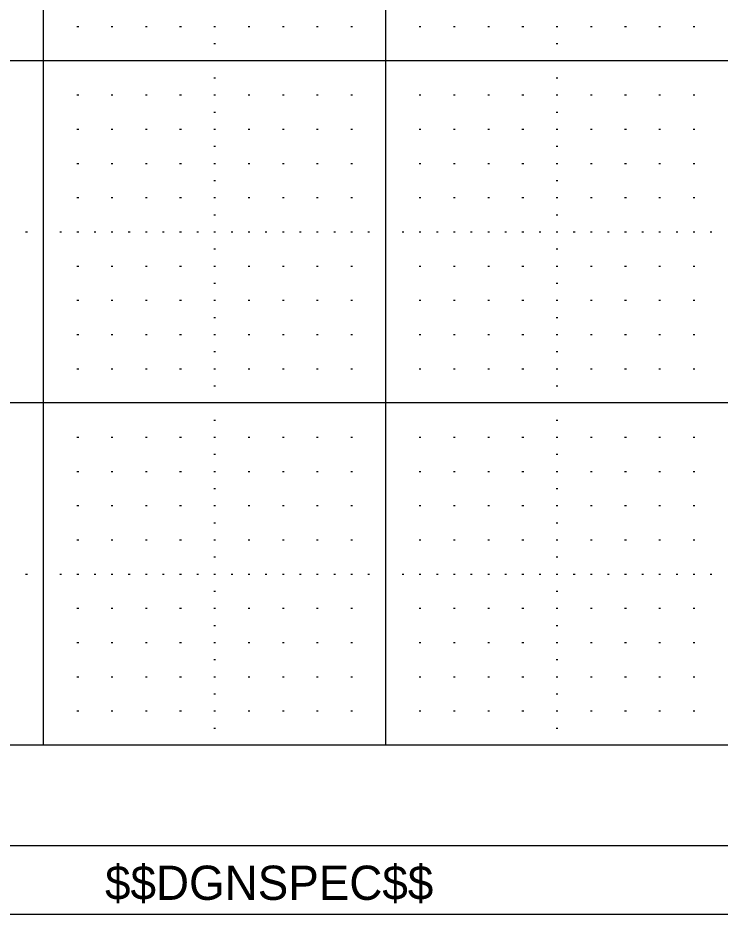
# Model space of a CAD drawing. Extents: x -1.3 to 32.1, y -0.2 to 20.7.
# Drawn here: x 21.67 to 23.721, y -0.2 to 2.418 of the extents above; entities that cross this region are included whole.
import ezdxf

# ---------------------------------------------------------------- set-up
doc = ezdxf.new("R2010")
doc.units = 0
for name, color, linetype in [('Level 1', 7, 'Continuous'), ('Level 4', 7, 'Continuous'), ('Level 48', 7, 'Continuous'), ('Level 5', 7, 'Continuous'), ('Level 63', 7, 'Continuous'), ('R_Border_Dark', 7, 'Continuous')]:
    doc.layers.add(name, color=color, linetype=linetype)

msp = doc.modelspace()

# ---------------------------------------------------------------- linework, layer by layer
at = {"layer": 'Level 1'}
msp.add_line((31.617, -0.001), (-0.001, -0.001), dxfattribs=at)
at = {"layer": 'Level 4'}
msp.add_line((31.617, 0.293), (-0.001, 0.293), dxfattribs=at)
at = {"layer": 'Level 5'}
for p, q in [((21.8425, 2.393), (21.8475, 2.393)), ((21.9425, 2.393), (21.9475, 2.393)), ((22.0425, 2.393), (22.0475, 2.393)), ((22.1425, 2.393), (22.1475, 2.393)), ((22.2425, 2.393), (22.2475, 2.393)), ((22.3425, 2.393), (22.3475, 2.393)), ((22.4425, 2.393), (22.4475, 2.393)), ((22.5425, 2.393), (22.5475, 2.393)), ((22.6425, 2.393), (22.6475, 2.393)), ((22.8425, 2.393), (22.8475, 2.393)), ((22.9425, 2.393), (22.9475, 2.393)), ((23.0425, 2.393), (23.0475, 2.393)), ((23.1425, 2.393), (23.1475, 2.393)), ((23.2425, 2.393), (23.2475, 2.393)), ((23.3425, 2.393), (23.3475, 2.393)), ((23.4425, 2.393), (23.4475, 2.393)), ((23.5425, 2.393), (23.5475, 2.393)), ((23.6425, 2.393), (23.6475, 2.393)), ((22.2425, 2.343), (22.2475, 2.343)), ((23.2425, 2.343), (23.2475, 2.343)), ((22.2425, 2.243), (22.2475, 2.243)), ((23.2425, 2.243), (23.2475, 2.243)), ((21.8425, 2.193), (21.8475, 2.193)), ((21.9425, 2.193), (21.9475, 2.193)), ((22.0425, 2.193), (22.0475, 2.193)), ((22.1425, 2.193), (22.1475, 2.193)), ((22.2425, 2.193), (22.2475, 2.193)), ((22.3425, 2.193), (22.3475, 2.193)), ((22.4425, 2.193), (22.4475, 2.193)), ((22.5425, 2.193), (22.5475, 2.193)), ((22.6425, 2.193), (22.6475, 2.193)), ((22.8425, 2.193), (22.8475, 2.193)), ((22.9425, 2.193), (22.9475, 2.193)), ((23.0425, 2.193), (23.0475, 2.193)), ((23.1425, 2.193), (23.1475, 2.193)), ((23.2425, 2.193), (23.2475, 2.193)), ((23.3425, 2.193), (23.3475, 2.193)), ((23.4425, 2.193), (23.4475, 2.193)), ((23.5425, 2.193), (23.5475, 2.193)), ((23.6425, 2.193), (23.6475, 2.193)), ((22.2425, 2.143), (22.2475, 2.143)), ((23.2425, 2.143), (23.2475, 2.143)), ((21.8425, 2.093), (21.8475, 2.093)), ((21.9425, 2.093), (21.9475, 2.093)), ((22.0425, 2.093), (22.0475, 2.093)), ((22.1425, 2.093), (22.1475, 2.093)), ((22.2425, 2.093), (22.2475, 2.093)), ((22.3425, 2.093), (22.3475, 2.093)), ((22.4425, 2.093), (22.4475, 2.093)), ((22.5425, 2.093), (22.5475, 2.093)), ((22.6425, 2.093), (22.6475, 2.093)), ((22.8425, 2.093), (22.8475, 2.093)), ((22.9425, 2.093), (22.9475, 2.093)), ((23.0425, 2.093), (23.0475, 2.093)), ((23.1425, 2.093), (23.1475, 2.093)), ((23.2425, 2.093), (23.2475, 2.093)), ((23.3425, 2.093), (23.3475, 2.093)), ((23.4425, 2.093), (23.4475, 2.093)), ((23.5425, 2.093), (23.5475, 2.093)), ((23.6425, 2.093), (23.6475, 2.093)), ((22.2425, 2.043), (22.2475, 2.043)), ((23.2425, 2.043), (23.2475, 2.043)), ((21.8425, 1.993), (21.8475, 1.993)), ((21.9425, 1.993), (21.9475, 1.993)), ((22.0425, 1.993), (22.0475, 1.993)), ((22.1425, 1.993), (22.1475, 1.993)), ((22.2425, 1.993), (22.2475, 1.993)), ((22.3425, 1.993), (22.3475, 1.993)), ((22.4425, 1.993), (22.4475, 1.993)), ((22.5425, 1.993), (22.5475, 1.993)), ((22.6425, 1.993), (22.6475, 1.993)), ((22.8425, 1.993), (22.8475, 1.993)), ((22.9425, 1.993), (22.9475, 1.993)), ((23.0425, 1.993), (23.0475, 1.993)), ((23.1425, 1.993), (23.1475, 1.993)), ((23.2425, 1.993), (23.2475, 1.993)), ((23.3425, 1.993), (23.3475, 1.993)), ((23.4425, 1.993), (23.4475, 1.993)), ((23.5425, 1.993), (23.5475, 1.993)), ((23.6425, 1.993), (23.6475, 1.993)), ((22.2425, 1.943), (22.2475, 1.943)), ((23.2425, 1.943), (23.2475, 1.943)), ((21.8425, 1.893), (21.8475, 1.893)), ((21.9425, 1.893), (21.9475, 1.893)), ((22.0425, 1.893), (22.0475, 1.893)), ((22.1425, 1.893), (22.1475, 1.893)), ((22.2425, 1.893), (22.2475, 1.893)), ((22.3425, 1.893), (22.3475, 1.893)), ((22.4425, 1.893), (22.4475, 1.893)), ((22.5425, 1.893), (22.5475, 1.893)), ((22.6425, 1.893), (22.6475, 1.893)), ((22.8425, 1.893), (22.8475, 1.893)), ((22.9425, 1.893), (22.9475, 1.893)), ((23.0425, 1.893), (23.0475, 1.893)), ((23.1425, 1.893), (23.1475, 1.893)), ((23.2425, 1.893), (23.2475, 1.893)), ((23.3425, 1.893), (23.3475, 1.893)), ((23.4425, 1.893), (23.4475, 1.893)), ((23.5425, 1.893), (23.5475, 1.893)), ((23.6425, 1.893), (23.6475, 1.893)), ((22.2425, 1.843), (22.2475, 1.843)), ((23.2425, 1.843), (23.2475, 1.843)), ((21.6925, 1.793), (21.6975, 1.793)), ((21.7925, 1.793), (21.7975, 1.793)), ((21.8425, 1.793), (21.8475, 1.793)), ((21.8925, 1.793), (21.8975, 1.793)), ((21.9425, 1.793), (21.9475, 1.793)), ((21.9925, 1.793), (21.9975, 1.793)), ((22.0425, 1.793), (22.0475, 1.793)), ((22.0925, 1.793), (22.0975, 1.793)), ((22.1425, 1.793), (22.1475, 1.793)), ((22.1925, 1.793), (22.1975, 1.793)), ((22.2425, 1.793), (22.2475, 1.793)), ((22.2925, 1.793), (22.2975, 1.793)), ((22.3425, 1.793), (22.3475, 1.793)), ((22.3925, 1.793), (22.3975, 1.793)), ((22.4425, 1.793), (22.4475, 1.793)), ((22.4925, 1.793), (22.4975, 1.793)), ((22.5425, 1.793), (22.5475, 1.793)), ((22.5925, 1.793), (22.5975, 1.793)), ((22.6425, 1.793), (22.6475, 1.793)), ((22.6925, 1.793), (22.6975, 1.793)), ((22.7925, 1.793), (22.7975, 1.793)), ((22.8425, 1.793), (22.8475, 1.793)), ((22.8925, 1.793), (22.8975, 1.793)), ((22.9425, 1.793), (22.9475, 1.793)), ((22.9925, 1.793), (22.9975, 1.793)), ((23.0425, 1.793), (23.0475, 1.793)), ((23.0925, 1.793), (23.0975, 1.793)), ((23.1425, 1.793), (23.1475, 1.793)), ((23.1925, 1.793), (23.1975, 1.793)), ((23.2425, 1.793), (23.2475, 1.793)), ((23.2925, 1.793), (23.2975, 1.793)), ((23.3425, 1.793), (23.3475, 1.793)), ((23.3925, 1.793), (23.3975, 1.793)), ((23.4425, 1.793), (23.4475, 1.793)), ((23.4925, 1.793), (23.4975, 1.793)), ((23.5425, 1.793), (23.5475, 1.793)), ((23.5925, 1.793), (23.5975, 1.793)), ((23.6425, 1.793), (23.6475, 1.793)), ((23.6925, 1.793), (23.6975, 1.793)), ((22.2425, 1.743), (22.2475, 1.743)), ((23.2425, 1.743), (23.2475, 1.743)), ((21.8425, 1.693), (21.8475, 1.693)), ((21.9425, 1.693), (21.9475, 1.693)), ((22.0425, 1.693), (22.0475, 1.693)), ((22.1425, 1.693), (22.1475, 1.693)), ((22.2425, 1.693), (22.2475, 1.693)), ((22.3425, 1.693), (22.3475, 1.693)), ((22.4425, 1.693), (22.4475, 1.693)), ((22.5425, 1.693), (22.5475, 1.693)), ((22.6425, 1.693), (22.6475, 1.693)), ((22.8425, 1.693), (22.8475, 1.693)), ((22.9425, 1.693), (22.9475, 1.693)), ((23.0425, 1.693), (23.0475, 1.693)), ((23.1425, 1.693), (23.1475, 1.693)), ((23.2425, 1.693), (23.2475, 1.693)), ((23.3425, 1.693), (23.3475, 1.693)), ((23.4425, 1.693), (23.4475, 1.693)), ((23.5425, 1.693), (23.5475, 1.693)), ((23.6425, 1.693), (23.6475, 1.693)), ((22.2425, 1.643), (22.2475, 1.643)), ((23.2425, 1.643), (23.2475, 1.643)), ((21.8425, 1.593), (21.8475, 1.593)), ((21.9425, 1.593), (21.9475, 1.593)), ((22.0425, 1.593), (22.0475, 1.593)), ((22.1425, 1.593), (22.1475, 1.593)), ((22.2425, 1.593), (22.2475, 1.593)), ((22.3425, 1.593), (22.3475, 1.593)), ((22.4425, 1.593), (22.4475, 1.593)), ((22.5425, 1.593), (22.5475, 1.593)), ((22.6425, 1.593), (22.6475, 1.593)), ((22.8425, 1.593), (22.8475, 1.593)), ((22.9425, 1.593), (22.9475, 1.593)), ((23.0425, 1.593), (23.0475, 1.593)), ((23.1425, 1.593), (23.1475, 1.593)), ((23.2425, 1.593), (23.2475, 1.593)), ((23.3425, 1.593), (23.3475, 1.593)), ((23.4425, 1.593), (23.4475, 1.593)), ((23.5425, 1.593), (23.5475, 1.593)), ((23.6425, 1.593), (23.6475, 1.593)), ((22.2425, 1.543), (22.2475, 1.543)), ((23.2425, 1.543), (23.2475, 1.543)), ((21.8425, 1.493), (21.8475, 1.493)), ((21.9425, 1.493), (21.9475, 1.493)), ((22.0425, 1.493), (22.0475, 1.493)), ((22.1425, 1.493), (22.1475, 1.493)), ((22.2425, 1.493), (22.2475, 1.493)), ((22.3425, 1.493), (22.3475, 1.493)), ((22.4425, 1.493), (22.4475, 1.493)), ((22.5425, 1.493), (22.5475, 1.493)), ((22.6425, 1.493), (22.6475, 1.493)), ((22.8425, 1.493), (22.8475, 1.493)), ((22.9425, 1.493), (22.9475, 1.493)), ((23.0425, 1.493), (23.0475, 1.493)), ((23.1425, 1.493), (23.1475, 1.493)), ((23.2425, 1.493), (23.2475, 1.493)), ((23.3425, 1.493), (23.3475, 1.493)), ((23.4425, 1.493), (23.4475, 1.493)), ((23.5425, 1.493), (23.5475, 1.493)), ((23.6425, 1.493), (23.6475, 1.493)), ((22.2425, 1.443), (22.2475, 1.443)), ((23.2425, 1.443), (23.2475, 1.443)), ((21.8425, 1.393), (21.8475, 1.393)), ((21.9425, 1.393), (21.9475, 1.393)), ((22.0425, 1.393), (22.0475, 1.393)), ((22.1425, 1.393), (22.1475, 1.393)), ((22.2425, 1.393), (22.2475, 1.393)), ((22.3425, 1.393), (22.3475, 1.393)), ((22.4425, 1.393), (22.4475, 1.393)), ((22.5425, 1.393), (22.5475, 1.393)), ((22.6425, 1.393), (22.6475, 1.393)), ((22.8425, 1.393), (22.8475, 1.393)), ((22.9425, 1.393), (22.9475, 1.393)), ((23.0425, 1.393), (23.0475, 1.393)), ((23.1425, 1.393), (23.1475, 1.393)), ((23.2425, 1.393), (23.2475, 1.393)), ((23.3425, 1.393), (23.3475, 1.393)), ((23.4425, 1.393), (23.4475, 1.393)), ((23.5425, 1.393), (23.5475, 1.393)), ((23.6425, 1.393), (23.6475, 1.393)), ((22.2425, 1.343), (22.2475, 1.343)), ((23.2425, 1.343), (23.2475, 1.343)), ((22.2425, 1.243), (22.2475, 1.243)), ((23.2425, 1.243), (23.2475, 1.243)), ((21.8425, 1.193), (21.8475, 1.193)), ((21.9425, 1.193), (21.9475, 1.193)), ((22.0425, 1.193), (22.0475, 1.193)), ((22.1425, 1.193), (22.1475, 1.193)), ((22.2425, 1.193), (22.2475, 1.193)), ((22.3425, 1.193), (22.3475, 1.193)), ((22.4425, 1.193), (22.4475, 1.193)), ((22.5425, 1.193), (22.5475, 1.193)), ((22.6425, 1.193), (22.6475, 1.193)), ((22.8425, 1.193), (22.8475, 1.193)), ((22.9425, 1.193), (22.9475, 1.193)), ((23.0425, 1.193), (23.0475, 1.193)), ((23.1425, 1.193), (23.1475, 1.193)), ((23.2425, 1.193), (23.2475, 1.193)), ((23.3425, 1.193), (23.3475, 1.193)), ((23.4425, 1.193), (23.4475, 1.193)), ((23.5425, 1.193), (23.5475, 1.193)), ((23.6425, 1.193), (23.6475, 1.193)), ((22.2425, 1.143), (22.2475, 1.143)), ((23.2425, 1.143), (23.2475, 1.143)), ((21.8425, 1.093), (21.8475, 1.093)), ((21.9425, 1.093), (21.9475, 1.093)), ((22.0425, 1.093), (22.0475, 1.093)), ((22.1425, 1.093), (22.1475, 1.093)), ((22.2425, 1.093), (22.2475, 1.093)), ((22.3425, 1.093), (22.3475, 1.093)), ((22.4425, 1.093), (22.4475, 1.093)), ((22.5425, 1.093), (22.5475, 1.093)), ((22.6425, 1.093), (22.6475, 1.093)), ((22.8425, 1.093), (22.8475, 1.093)), ((22.9425, 1.093), (22.9475, 1.093)), ((23.0425, 1.093), (23.0475, 1.093)), ((23.1425, 1.093), (23.1475, 1.093)), ((23.2425, 1.093), (23.2475, 1.093)), ((23.3425, 1.093), (23.3475, 1.093)), ((23.4425, 1.093), (23.4475, 1.093)), ((23.5425, 1.093), (23.5475, 1.093)), ((23.6425, 1.093), (23.6475, 1.093)), ((22.2425, 1.043), (22.2475, 1.043)), ((23.2425, 1.043), (23.2475, 1.043)), ((21.8425, 0.993), (21.8475, 0.993)), ((21.9425, 0.993), (21.9475, 0.993)), ((22.0425, 0.993), (22.0475, 0.993)), ((22.1425, 0.993), (22.1475, 0.993)), ((22.2425, 0.993), (22.2475, 0.993)), ((22.3425, 0.993), (22.3475, 0.993)), ((22.4425, 0.993), (22.4475, 0.993)), ((22.5425, 0.993), (22.5475, 0.993)), ((22.6425, 0.993), (22.6475, 0.993)), ((22.8425, 0.993), (22.8475, 0.993)), ((22.9425, 0.993), (22.9475, 0.993)), ((23.0425, 0.993), (23.0475, 0.993)), ((23.1425, 0.993), (23.1475, 0.993)), ((23.2425, 0.993), (23.2475, 0.993)), ((23.3425, 0.993), (23.3475, 0.993)), ((23.4425, 0.993), (23.4475, 0.993)), ((23.5425, 0.993), (23.5475, 0.993)), ((23.6425, 0.993), (23.6475, 0.993)), ((22.2425, 0.943), (22.2475, 0.943)), ((23.2425, 0.943), (23.2475, 0.943)), ((21.8425, 0.893), (21.8475, 0.893)), ((21.9425, 0.893), (21.9475, 0.893)), ((22.0425, 0.893), (22.0475, 0.893)), ((22.1425, 0.893), (22.1475, 0.893)), ((22.2425, 0.893), (22.2475, 0.893)), ((22.3425, 0.893), (22.3475, 0.893)), ((22.4425, 0.893), (22.4475, 0.893)), ((22.5425, 0.893), (22.5475, 0.893)), ((22.6425, 0.893), (22.6475, 0.893)), ((22.8425, 0.893), (22.8475, 0.893)), ((22.9425, 0.893), (22.9475, 0.893)), ((23.0425, 0.893), (23.0475, 0.893)), ((23.1425, 0.893), (23.1475, 0.893)), ((23.2425, 0.893), (23.2475, 0.893)), ((23.3425, 0.893), (23.3475, 0.893)), ((23.4425, 0.893), (23.4475, 0.893)), ((23.5425, 0.893), (23.5475, 0.893)), ((23.6425, 0.893), (23.6475, 0.893)), ((22.2425, 0.843), (22.2475, 0.843)), ((23.2425, 0.843), (23.2475, 0.843)), ((21.6925, 0.793), (21.6975, 0.793)), ((21.7925, 0.793), (21.7975, 0.793)), ((21.8425, 0.793), (21.8475, 0.793)), ((21.8925, 0.793), (21.8975, 0.793)), ((21.9425, 0.793), (21.9475, 0.793)), ((21.9925, 0.793), (21.9975, 0.793)), ((22.0425, 0.793), (22.0475, 0.793)), ((22.0925, 0.793), (22.0975, 0.793)), ((22.1425, 0.793), (22.1475, 0.793)), ((22.1925, 0.793), (22.1975, 0.793)), ((22.2425, 0.793), (22.2475, 0.793)), ((22.2925, 0.793), (22.2975, 0.793)), ((22.3425, 0.793), (22.3475, 0.793)), ((22.3925, 0.793), (22.3975, 0.793)), ((22.4425, 0.793), (22.4475, 0.793)), ((22.4925, 0.793), (22.4975, 0.793)), ((22.5425, 0.793), (22.5475, 0.793)), ((22.5925, 0.793), (22.5975, 0.793)), ((22.6425, 0.793), (22.6475, 0.793)), ((22.6925, 0.793), (22.6975, 0.793)), ((22.7925, 0.793), (22.7975, 0.793)), ((22.8425, 0.793), (22.8475, 0.793)), ((22.8925, 0.793), (22.8975, 0.793)), ((22.9425, 0.793), (22.9475, 0.793)), ((22.9925, 0.793), (22.9975, 0.793)), ((23.0425, 0.793), (23.0475, 0.793)), ((23.0925, 0.793), (23.0975, 0.793)), ((23.1425, 0.793), (23.1475, 0.793)), ((23.1925, 0.793), (23.1975, 0.793)), ((23.2425, 0.793), (23.2475, 0.793)), ((23.2925, 0.793), (23.2975, 0.793)), ((23.3425, 0.793), (23.3475, 0.793)), ((23.3925, 0.793), (23.3975, 0.793)), ((23.4425, 0.793), (23.4475, 0.793)), ((23.4925, 0.793), (23.4975, 0.793)), ((23.5425, 0.793), (23.5475, 0.793)), ((23.5925, 0.793), (23.5975, 0.793)), ((23.6425, 0.793), (23.6475, 0.793)), ((23.6925, 0.793), (23.6975, 0.793)), ((22.2425, 0.743), (22.2475, 0.743)), ((23.2425, 0.743), (23.2475, 0.743)), ((21.8425, 0.693), (21.8475, 0.693)), ((21.9425, 0.693), (21.9475, 0.693)), ((22.0425, 0.693), (22.0475, 0.693)), ((22.1425, 0.693), (22.1475, 0.693)), ((22.2425, 0.693), (22.2475, 0.693)), ((22.3425, 0.693), (22.3475, 0.693)), ((22.4425, 0.693), (22.4475, 0.693)), ((22.5425, 0.693), (22.5475, 0.693)), ((22.6425, 0.693), (22.6475, 0.693)), ((22.8425, 0.693), (22.8475, 0.693)), ((22.9425, 0.693), (22.9475, 0.693)), ((23.0425, 0.693), (23.0475, 0.693)), ((23.1425, 0.693), (23.1475, 0.693)), ((23.2425, 0.693), (23.2475, 0.693)), ((23.3425, 0.693), (23.3475, 0.693)), ((23.4425, 0.693), (23.4475, 0.693)), ((23.5425, 0.693), (23.5475, 0.693)), ((23.6425, 0.693), (23.6475, 0.693)), ((22.2425, 0.643), (22.2475, 0.643)), ((23.2425, 0.643), (23.2475, 0.643)), ((21.8425, 0.593), (21.8475, 0.593)), ((21.9425, 0.593), (21.9475, 0.593)), ((22.0425, 0.593), (22.0475, 0.593)), ((22.1425, 0.593), (22.1475, 0.593)), ((22.2425, 0.593), (22.2475, 0.593)), ((22.3425, 0.593), (22.3475, 0.593)), ((22.4425, 0.593), (22.4475, 0.593)), ((22.5425, 0.593), (22.5475, 0.593)), ((22.6425, 0.593), (22.6475, 0.593)), ((22.8425, 0.593), (22.8475, 0.593)), ((22.9425, 0.593), (22.9475, 0.593)), ((23.0425, 0.593), (23.0475, 0.593)), ((23.1425, 0.593), (23.1475, 0.593)), ((23.2425, 0.593), (23.2475, 0.593)), ((23.3425, 0.593), (23.3475, 0.593)), ((23.4425, 0.593), (23.4475, 0.593)), ((23.5425, 0.593), (23.5475, 0.593)), ((23.6425, 0.593), (23.6475, 0.593)), ((22.2425, 0.543), (22.2475, 0.543)), ((23.2425, 0.543), (23.2475, 0.543)), ((21.8425, 0.493), (21.8475, 0.493)), ((21.9425, 0.493), (21.9475, 0.493)), ((22.0425, 0.493), (22.0475, 0.493)), ((22.1425, 0.493), (22.1475, 0.493)), ((22.2425, 0.493), (22.2475, 0.493)), ((22.3425, 0.493), (22.3475, 0.493)), ((22.4425, 0.493), (22.4475, 0.493)), ((22.5425, 0.493), (22.5475, 0.493)), ((22.6425, 0.493), (22.6475, 0.493)), ((22.8425, 0.493), (22.8475, 0.493)), ((22.9425, 0.493), (22.9475, 0.493)), ((23.0425, 0.493), (23.0475, 0.493)), ((23.1425, 0.493), (23.1475, 0.493)), ((23.2425, 0.493), (23.2475, 0.493)), ((23.3425, 0.493), (23.3475, 0.493)), ((23.4425, 0.493), (23.4475, 0.493)), ((23.5425, 0.493), (23.5475, 0.493)), ((23.6425, 0.493), (23.6475, 0.493)), ((22.2425, 0.443), (22.2475, 0.443)), ((23.2425, 0.443), (23.2475, 0.443)), ((21.8425, 0.393), (21.8475, 0.393)), ((21.9425, 0.393), (21.9475, 0.393)), ((22.0425, 0.393), (22.0475, 0.393)), ((22.1425, 0.393), (22.1475, 0.393)), ((22.2425, 0.393), (22.2475, 0.393)), ((22.3425, 0.393), (22.3475, 0.393)), ((22.4425, 0.393), (22.4475, 0.393)), ((22.5425, 0.393), (22.5475, 0.393)), ((22.6425, 0.393), (22.6475, 0.393)), ((22.8425, 0.393), (22.8475, 0.393)), ((22.9425, 0.393), (22.9475, 0.393)), ((23.0425, 0.393), (23.0475, 0.393)), ((23.1425, 0.393), (23.1475, 0.393)), ((23.2425, 0.393), (23.2475, 0.393)), ((23.3425, 0.393), (23.3475, 0.393)), ((23.4425, 0.393), (23.4475, 0.393)), ((23.5425, 0.393), (23.5475, 0.393)), ((23.6425, 0.393), (23.6475, 0.393)), ((22.2425, 0.343), (22.2475, 0.343)), ((23.2425, 0.343), (23.2475, 0.343))]:
    msp.add_line(p, q, dxfattribs=at)
at = {"layer": 'Level 63'}
msp.add_lwpolyline([(-1.263, -0.2005), (32.067, -0.2005), (32.067, 20.7465), (-1.263, 20.7465)], close=True, dxfattribs=at)
msp.add_lwpolyline([(30.745, 8.293), (30.745, 0.293), (0.745, 0.293), (0.745, 8.293)], dxfattribs=at)
at = {"layer": 'R_Border_Dark'}
for p, q in [((21.745, 0.293), (21.745, 8.293)), ((22.745, 0.293), (22.745, 8.293)), ((31.617, 2.293), (-0.001, 2.293)), ((31.617, 1.293), (-0.001, 1.293))]:
    msp.add_line(p, q, dxfattribs=at)
msp.add_lwpolyline([(30.745, 8.293), (30.745, 0.293), (0.745, 0.293), (0.745, 8.293)], dxfattribs=at)

# ---------------------------------------------------------------- texts
at = {"layer": 'Level 48'}
msp.add_text('$$DGNSPEC$$', height=0.100002, dxfattribs=at).set_placement((21.9246, -0.159))

doc.saveas('drawing.dxf')
